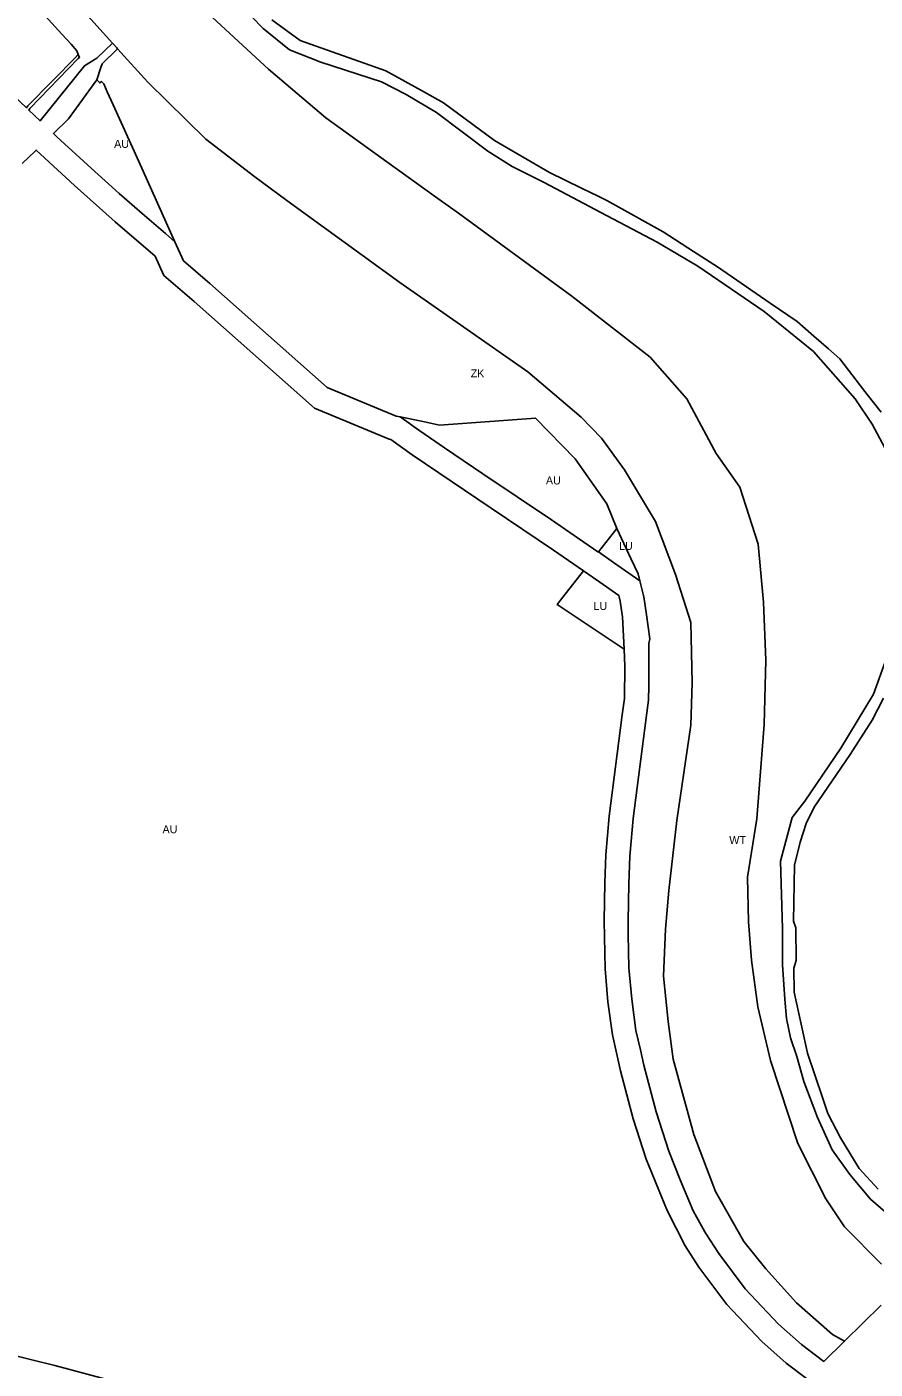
# Model space of a CAD drawing. Extents: x -545779 to -541342, y -1153413 to -1149956.
# Drawn here: x -543110 to -542580, y -1151300 to -1150461 of the extents above; entities that cross this region are included whole.
import ezdxf

# ---------------------------------------------------------------- set-up
doc = ezdxf.new("R2010")
doc.units = 0
for name, color, linetype in [('90640013', 7, 'Continuous'), ('90710013', 7, 'Continuous'), ('90750013', 7, 'Continuous'), ('90770013', 7, 'Continuous')]:
    doc.layers.add(name, color=color, linetype=linetype)

msp = doc.modelspace()

# ---------------------------------------------------------------- linework, layer by layer
at = {"layer": '90640013'}
for points in [[(-542576.24, -1151260.17), (-542599.22, -1151282.78), (-542606.75, -1151278.51), (-542629.27, -1151258.74), (-542648.37, -1151237.64), (-542662.09, -1151220.48), (-542679.85, -1151189.3), (-542693.46, -1151153.54), (-542706.26, -1151106.43), (-542709.32, -1151082.96), (-542712.28, -1151054.57), (-542711.12, -1151025.21), (-542708.98, -1151001.05), (-542704.01, -1150957.37), (-542695.25, -1150897.83), (-542694.4, -1150871.37), (-542695.3, -1150833.71), (-542704.75, -1150803.6), (-542717.27, -1150770.47), (-542736.65, -1150738.22), (-542750.99, -1150718.53), (-542763.83, -1150705.4), (-542797.14, -1150676.99), (-542877.1, -1150621.25), (-542947.61, -1150569.95), (-542967.7, -1150555.26), (-542998.29, -1150531.61), (-543034.45, -1150496.06), (-543053.37, -1150475.24), (-543053.95, -1150474.59), (-543056.04, -1150472.29), (-543056.63, -1150471.65), (-543076, -1150450.32)], [(-542994.14, -1150455.73), (-542959.14, -1150487.92), (-542923.23, -1150518.4), (-542885.11, -1150545.91), (-542853.27, -1150568.8), (-542840.3, -1150577.96), (-542769.53, -1150629.69), (-542720.62, -1150667.89), (-542697.73, -1150693.85), (-542679.4, -1150728.18), (-542664.57, -1150749.17), (-542653.18, -1150784.63), (-542649.87, -1150820.92), (-542648.38, -1150857.27), (-542649.36, -1150897.36), (-542654.05, -1150956.36), (-542659.77, -1150992.79), (-542659.3, -1151020.78), (-542657.28, -1151044.73), (-542653.32, -1151073.83), (-542645.43, -1151107.29), (-542628.38, -1151159.19), (-542610.81, -1151193.81), (-542599.21, -1151211.3), (-542576.07, -1151234.58)]]:
    msp.add_lwpolyline(points, dxfattribs=at)
at = {"layer": '90710013'}
for points in [[(-542983.39, -1150440.67), (-542962.35, -1150462.51), (-542945.93, -1150475.79), (-542926.35, -1150483.61), (-542888.45, -1150495.87), (-542873.16, -1150503.85), (-542854.19, -1150515.06), (-542822.11, -1150539.26), (-542806.95, -1150548.7), (-542786.83, -1150558.73), (-542751.54, -1150577.56), (-542716.17, -1150596.02), (-542690.78, -1150610.95), (-542649.47, -1150639.4), (-542618.67, -1150664.43), (-542592.51, -1150693.89), (-542581.97, -1150709.69), (-542572.32, -1150727.63)], [(-543076, -1150450.32), (-543056.63, -1150471.65), (-543066.46, -1150481.04), (-543069.043, -1150482.66), (-543074.08, -1150485.82), (-543101.822, -1150520.244), (-543108.935, -1150513.459), (-543108.19, -1150512.45), (-543077.98, -1150481.28), (-543077.28, -1150480.58), (-543077.94, -1150478.69), (-543078.75, -1150476.37), (-543082.43, -1150472.34), (-543088.15, -1150466.06), (-543104.73, -1150447.88)], [(-542576.07, -1151234.58), (-542599.21, -1151211.3), (-542610.81, -1151193.81), (-542628.38, -1151159.19), (-542645.43, -1151107.29), (-542653.32, -1151073.83), (-542657.28, -1151044.73), (-542659.3, -1151020.78), (-542659.77, -1150992.79), (-542654.05, -1150956.36), (-542649.36, -1150897.36), (-542648.38, -1150857.27), (-542649.87, -1150820.92), (-542653.18, -1150784.63), (-542664.57, -1150749.17), (-542679.4, -1150728.18), (-542697.73, -1150693.85), (-542720.62, -1150667.89), (-542769.53, -1150629.69), (-542840.3, -1150577.96), (-542853.27, -1150568.8), (-542885.11, -1150545.91), (-542923.23, -1150518.4), (-542959.14, -1150487.92), (-542994.14, -1150455.73)], [(-542567.63, -1150840.97), (-542581.09, -1150878.47), (-542601.49, -1150912.16), (-542624.02, -1150945.26), (-542631.93, -1150955.49), (-542639.22, -1150982.71), (-542638.05, -1151024.8), (-542637.98, -1151047.59), (-542636.43, -1151069), (-542635.51, -1151081.03), (-542633.03, -1151093.29), (-542629.05, -1151104.9), (-542624.64, -1151120.51), (-542616.12, -1151143.06), (-542607.01, -1151163.11), (-542595.99, -1151178.55), (-542582.93, -1151194.04), (-542567.35, -1151207.59)], [(-542990.46, -1151336.67), (-543163.961, -1151295.825), (-543180.77, -1151276.4), (-543166.94, -1151279.89), (-543145.84, -1151284.58), (-543106.07, -1151294.56), (-543092.51, -1151297.96), (-543052.23, -1151308.78)]]:
    msp.add_lwpolyline(points, dxfattribs=at)
msp.add_lwpolyline([(-542599.22, -1151282.78), (-542612.07, -1151295.42), (-542626.16, -1151284.79), (-542640.42, -1151272.17), (-542661.27, -1151250.07), (-542677.84, -1151227.91), (-542685.84, -1151215.55), (-542686.54, -1151214.47), (-542693.68, -1151201.29), (-542696.44, -1151194.85), (-542701.98, -1151181.96), (-542708.99, -1151163.91), (-542716.97, -1151139.53), (-542724.61, -1151110.24), (-542726.76, -1151100.72), (-542729.5, -1151088.58), (-542732.15, -1151069.03), (-542733.87, -1151049.36), (-542734.3, -1151028.54), (-542734.48, -1151020.04), (-542733.99, -1150996.89), (-542733.27, -1150979.77), (-542733.04, -1150977.32), (-542731.37, -1150956.16), (-542723.19, -1150893.25), (-542721.75, -1150882.21), (-542721.713, -1150881.186), (-542721.46, -1150874.27), (-542721.43, -1150860.66), (-542721.41, -1150853.81), (-542721.4, -1150846.72), (-542720.95, -1150843.81), (-542723.025, -1150828.79), (-542724.58, -1150817.54), (-542727.122, -1150807.586), (-542728.24, -1150803.21), (-542732.72, -1150793.68), (-542741.51, -1150774.97), (-542747.62, -1150759.55), (-542767.48, -1150731.43), (-542792.22, -1150705.95), (-542852.21, -1150710.28), (-542863.52, -1150707.95), (-542876.817, -1150705.217), (-542879.33, -1150704.7), (-542922.39, -1150686.8), (-542995.69, -1150621.83), (-543012.19, -1150607.72), (-543017.596, -1150595.722), (-543040.16, -1150545.65), (-543056.14, -1150510.18), (-543059.81, -1150502.04), (-543062.08, -1150497), (-543063.52, -1150495.61), (-543064.51, -1150496.55), (-543066.32, -1150494.52), (-543063.887, -1150486.947), (-543063.12, -1150484.56), (-543053.37, -1150475.24), (-543034.45, -1150496.06), (-542998.29, -1150531.61), (-542967.7, -1150555.26), (-542947.61, -1150569.95), (-542877.1, -1150621.25), (-542797.14, -1150676.99), (-542763.83, -1150705.4), (-542750.99, -1150718.53), (-542736.65, -1150738.22), (-542717.27, -1150770.47), (-542704.75, -1150803.6), (-542695.3, -1150833.71), (-542694.4, -1150871.37), (-542695.25, -1150897.83), (-542704.01, -1150957.37), (-542708.98, -1151001.05), (-542711.12, -1151025.21), (-542712.28, -1151054.57), (-542709.32, -1151082.96), (-542706.26, -1151106.43), (-542693.46, -1151153.54), (-542679.85, -1151189.3), (-542662.09, -1151220.48), (-542648.37, -1151237.64), (-542629.27, -1151258.74), (-542606.75, -1151278.51)], close=True, dxfattribs=at)
at = {"layer": '90750013'}
for points in [[(-543104.73, -1150447.88), (-543088.15, -1150466.06), (-543082.43, -1150472.34), (-543078.75, -1150476.37), (-543077.94, -1150478.69), (-543078.97, -1150479.78), (-543079.12, -1150479.93), (-543109.47, -1150510.9), (-543110.38, -1150512.08), (-543118.844, -1150504.007), (-543132.527, -1150490.655), (-543162.992, -1150460.034)], [(-542576.23, -1150702.32), (-542585.01, -1150691.28), (-542586.51, -1150689.38), (-542602.24, -1150669.02), (-542609.26, -1150662.77), (-542618.41, -1150654.69), (-542628.79, -1150645.63), (-542645.66, -1150634.13), (-542678.6, -1150611.44), (-542693.55, -1150601.76), (-542712.51, -1150589.48), (-542747.63, -1150570.02), (-542752.7, -1150567.55), (-542763.51, -1150562.3), (-542783.62, -1150552.52), (-542817.82, -1150532.5), (-542849.86, -1150508.94), (-542861.66, -1150502.34), (-542885.74, -1150488.88), (-542939.27, -1150470.05), (-542957.08, -1150457.18)], [(-543112.93, -1150546.93), (-543104.97, -1150539.21), (-543104.271, -1150538.531), (-543101.53, -1150541.133), (-543080.232, -1150560.722), (-543054.91, -1150583.328), (-543029.924, -1150604.876), (-543024.488, -1150616.94), (-543005.54, -1150633.143), (-542930.463, -1150699.688), (-542883.759, -1150719.103), (-542882.77, -1150719.307), (-542882.77, -1150719.307), (-542869.289, -1150728.873), (-542820.014, -1150762.285), (-542781.085, -1150788.56), (-542762.317, -1150801.459), (-542775.27, -1150817.95), (-542778.77, -1150822.41), (-542736.97, -1150850.244), (-542736.435, -1150860.924), (-542736.735, -1150881.125), (-542738.064, -1150891.313), (-542746.292, -1150954.59), (-542748.245, -1150978.853), (-542748.983, -1150996.416), (-542749.483, -1151020.037), (-542748.856, -1151050.17), (-542747.062, -1151070.692), (-542744.276, -1151091.244), (-542739.187, -1151113.786), (-542731.368, -1151143.76), (-542723.085, -1151169.068), (-542710.092, -1151201.1), (-542698.845, -1151223.063), (-542690.157, -1151236.486), (-542672.769, -1151259.74), (-542650.867, -1151282.955), (-542635.662, -1151296.411), (-542622.881, -1151306.054)], [(-542578.28, -1151187.68), (-542590.02, -1151174.76), (-542601.81, -1151155.76), (-542609.63, -1151140.42), (-542612.76, -1151131.18), (-542622.37, -1151102.81), (-542623.4, -1151098.08), (-542630.67, -1151064.57), (-542630.81, -1151049.59), (-542629.35, -1151044.93), (-542629.55, -1151024.45), (-542630.99, -1151020.31), (-542630.5, -1150985.34), (-542626.89, -1150970.85), (-542623.17, -1150959.34), (-542618.19, -1150949.13), (-542595.71, -1150916.11), (-542581.96, -1150894.8), (-542574.79, -1150881.02)], [(-543052.23, -1151308.78), (-543092.51, -1151297.96), (-543106.07, -1151294.56), (-543145.84, -1151284.58)]]:
    msp.add_lwpolyline(points, dxfattribs=at)
for points in [[(-543091.287, -1150530.174), (-543093.514, -1150528.088), (-543084.05, -1150518.91), (-543066.32, -1150494.52), (-543064.51, -1150496.55), (-543063.52, -1150495.61), (-543062.08, -1150497), (-543059.81, -1150502.04), (-543056.14, -1150510.18), (-543040.16, -1150545.65), (-543017.596, -1150595.722), (-543023.498, -1150590.698), (-543037.995, -1150578.194), (-543052.36, -1150565.571), (-543069.987, -1150549.764)], [(-542872.654, -1150708.173), (-542876.817, -1150705.217), (-542863.52, -1150707.95), (-542852.21, -1150710.28), (-542792.22, -1150705.95), (-542767.48, -1150731.43), (-542747.62, -1150759.55), (-542741.51, -1150774.97), (-542753.015, -1150789.617), (-542753.015, -1150789.617), (-542753.25, -1150789.455), (-542782.363, -1150769.55), (-542825.268, -1150740.761), (-542849.156, -1150724.571), (-542864.645, -1150713.816), (-542868.745, -1150710.935)]]:
    msp.add_lwpolyline(points, close=True, dxfattribs=at)
at = {"layer": '90770013'}
for points in [[(-542753.015, -1150789.617), (-542741.51, -1150774.97), (-542732.72, -1150793.68), (-542728.24, -1150803.21), (-542727.122, -1150807.586), (-542733.911, -1150802.849), (-542743.575, -1150796.138)], [(-542736.97, -1150850.244), (-542778.77, -1150822.41), (-542775.27, -1150817.95), (-542762.317, -1150801.459), (-542752.108, -1150808.475), (-542740.273, -1150816.714), (-542739.323, -1150820.432), (-542737.974, -1150830.194)]]:
    msp.add_lwpolyline(points, close=True, dxfattribs=at)

# ---------------------------------------------------------------- texts
at = {"layer": '90640013'}
msp.add_text('WT', height=5, rotation=360, dxfattribs=at).set_placement((-542671.195, -1150972.144))
at = {"layer": '90710013'}
msp.add_text('ZK', height=5, rotation=0, dxfattribs=at).set_placement((-542832.77, -1150680.515))
at = {"layer": '90750013'}
for rotation, p in [(0, (-543055.555, -1150537.092)), (0, (-542785.769, -1150747.417)), (360, (-543025.31, -1150965.396))]:
    msp.add_text('AU', height=5, rotation=rotation, dxfattribs=at).set_placement(p)
at = {"layer": '90770013'}
for p in [(-542740.069, -1150788.306), (-542756.088, -1150825.851)]:
    msp.add_text('LU', height=5, rotation=360, dxfattribs=at).set_placement(p)

doc.saveas('drawing.dxf')
